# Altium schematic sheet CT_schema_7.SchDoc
size 277 x 170 mm
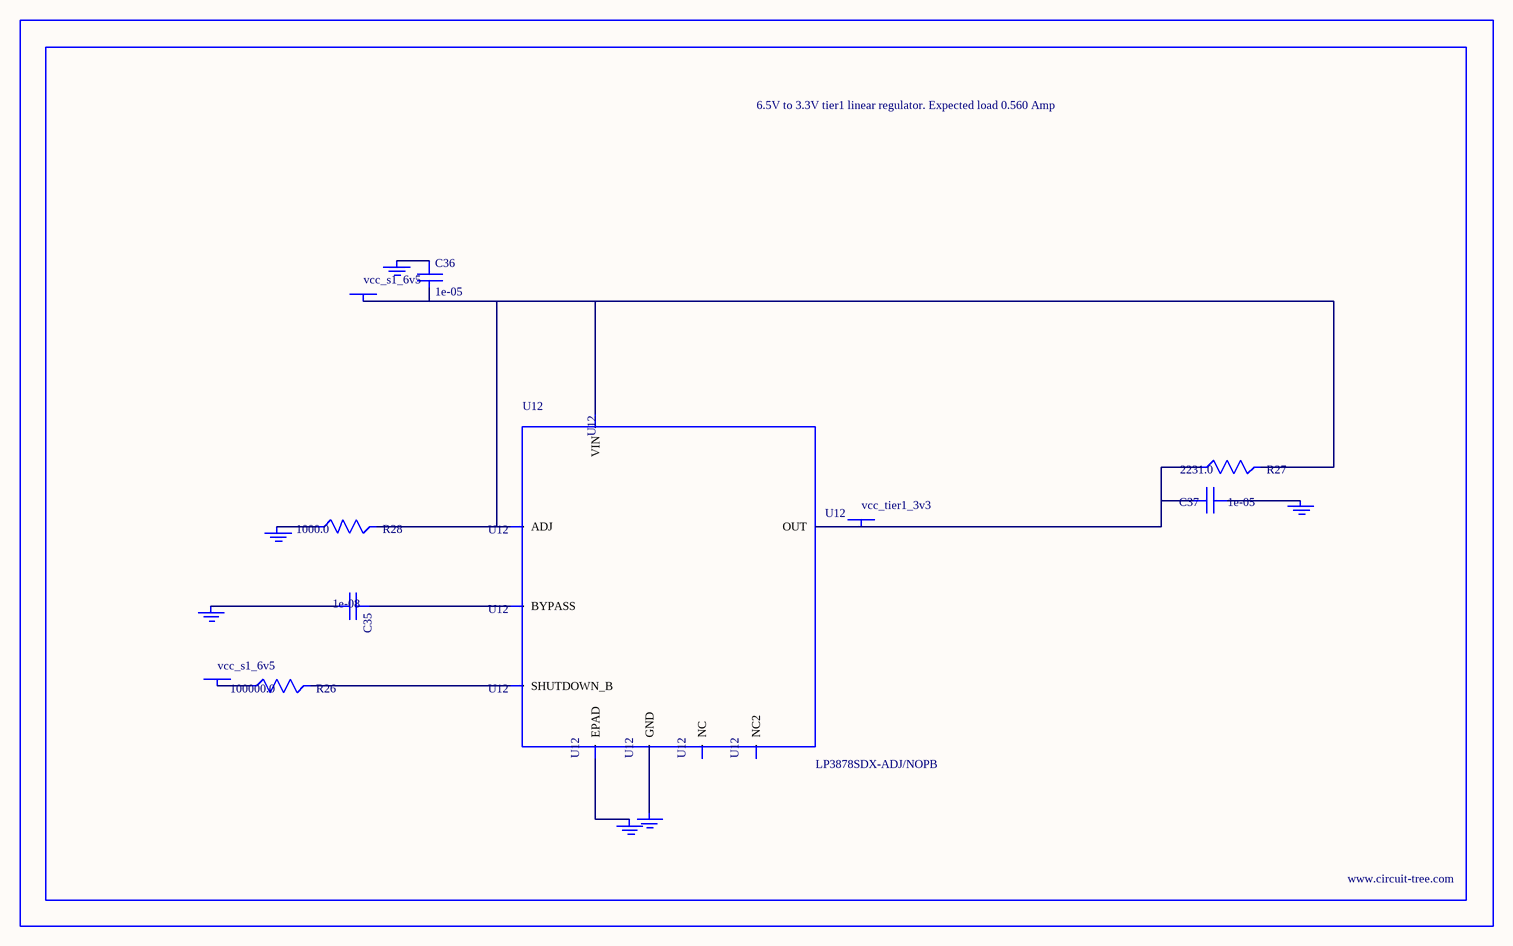
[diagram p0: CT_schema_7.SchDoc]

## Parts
BORDER6  (no value)
C35  1e-08  [C0402]
C36  1e-05  [C1206]
C37  1e-05  [C1210]
GND_INSTANCE_6_0  (no value)
GND_INSTANCE_6_1  (no value)
GND_INSTANCE_6_2  (no value)
GND_INSTANCE_6_3  (no value)
GND_INSTANCE_6_4  (no value)
GND_INSTANCE_6_5  (no value)
POWER_INSTANCE_6_0  vcc_s1_6v5
POWER_INSTANCE_6_1  vcc_s1_6v5
POWER_INSTANCE_6_2  vcc_tier1_3v3
R26  100000.0  [R0603]
R27  2231.0  [R0603]
R28  1000.0  [R0603]
U12  LP3878SDX-ADJ/NOPB  [WSON-8]

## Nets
NetC35_1: C35.1 U12.1(BYPASS)
NetC35_2: C35.2 GND_INSTANCE_6_0.0(GND)
NetC36_1: C36.1 GND_INSTANCE_6_1.0(GND)
NetC36_2: C36.2 POWER_INSTANCE_6_0.0(PWR) R27.2 R28.2 U12.4(VIN) U12.6(ADJ)
NetC37_1: C37.1 GND_INSTANCE_6_2.0(GND)
NetC37_2: C37.2 POWER_INSTANCE_6_2.0(PWR) R27.1 U12.5(OUT)
NetGND_INSTANCE_6_3_0: GND_INSTANCE_6_3.0(GND) R28.1
NetGND_INSTANCE_6_4_0: GND_INSTANCE_6_4.0(GND) U12.PAD(EPAD)
NetGND_INSTANCE_6_5_0: GND_INSTANCE_6_5.0(GND) U12.3(GND)
NetPOWER_INSTANCE_6_1_0: POWER_INSTANCE_6_1.0(PWR) R26.1
NetR26_2: R26.2 U12.8(SHUTDOWN_B)

Not connected (* = marked no-connect by the designer): U12 2(NC) 7(NC2)

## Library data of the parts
BORDER6 = BORDER_PAGE6
C35 = C0402C103K3RAC
C36 = C1206C106K3RACTU
C37 = GRM32DR61E106MA12L
GND_INSTANCE_6_0-GND_INSTANCE_6_5 = GND
POWER_INSTANCE_6_0-POWER_INSTANCE_6_2 = PWR
R26 = RC0603JR-07100KL
R27 = R27
R28 = RC0603JR-071KL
